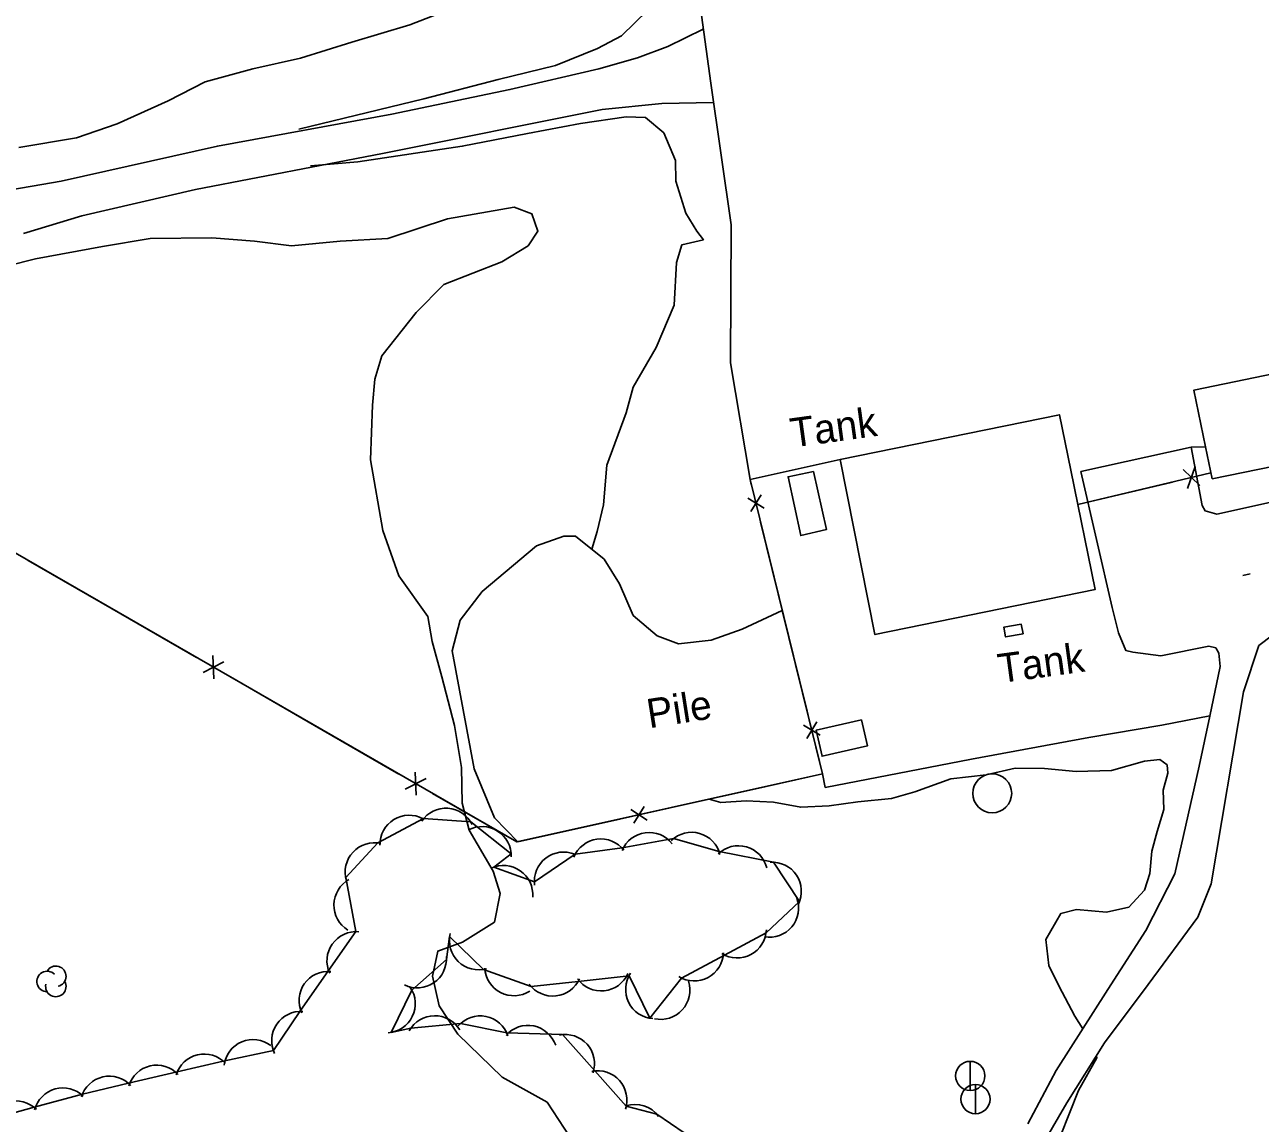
# Model space of a CAD drawing. Extents: x 643342 to 646936, y 5873857 to 5876103.
# Drawn here: x 645862.1 to 645989.1, y 5875514.5 to 5875627.4 of the extents above; entities that cross this region are included whole.
import ezdxf

# ---------------------------------------------------------------- set-up
doc = ezdxf.new("R2010")
doc.units = 0
for name, color, linetype in [('Niveau 19', 7, 'Continuous'), ('Niveau 2', 7, 'Continuous'), ('Niveau 21', 7, 'Continuous'), ('Niveau 3', 7, 'Continuous'), ('Niveau 31', 7, 'Continuous'), ('Niveau 33', 7, 'Continuous'), ('Niveau 36', 7, 'Continuous'), ('Niveau 37', 7, 'Continuous'), ('Niveau 44', 7, 'Continuous'), ('Niveau 57', 7, 'Continuous')]:
    doc.layers.add(name, color=color, linetype=linetype)

msp = doc.modelspace()

# ---------------------------------------------------------------- linework, layer by layer
at = {"layer": 'Niveau 19'}
for points in [[(645936.63, 5875580.67), (645934.6, 5875592.65), (645934.67, 5875606.84), (645932.59, 5875621.38), (645931.38, 5875630.15), (645932.04, 5875643.22), (645932.85, 5875648.57), (645934.53, 5875650.39), (645937.1, 5875651.48), (645954.04, 5875654.92), (645956.53, 5875656.71), (645957.95, 5875658.73), (645958.33, 5875660.53), (645958.77, 5875662.91), (645956.04, 5875678.99), (645953.32, 5875691.9), (645950.59, 5875700.71), (645949.61, 5875703.18), (645944.67, 5875717.25)], [(645981.95, 5875583.99), (645983.44, 5875584.02)], [(645944.08, 5875550.42), (645944.35, 5875549.04), (645959.39, 5875551.93), (645971.45, 5875554.15), (645978.93, 5875555.42), (645983.87, 5875556.38)]]:
    msp.add_lwpolyline(points, dxfattribs=at)
at = {"layer": 'Niveau 2'}
for points in [[(645861.47, 5875614.78), (645867.4, 5875615.77), (645871.59, 5875617.21), (645876.84, 5875619.59), (645880.62, 5875621.51), (645885.52, 5875622.86), (645890.44, 5875623.97), (645895.72, 5875625.59), (645901.68, 5875627.39), (645908.21, 5875629.91)], [(645926.12, 5875628.89), (645923.43, 5875626.26), (645920.94, 5875624.94), (645916.62, 5875623.2), (645910.74, 5875621.75), (645903.11, 5875619.77), (645890.27, 5875616.68)], [(645920.35, 5875573.52), (645920.91, 5875575.34), (645921.55, 5875578.05), (645921.92, 5875582.14), (645923.9, 5875587.51), (645924.61, 5875590.17), (645926.97, 5875594.23), (645928.83, 5875598.59), (645929.05, 5875602.95), (645929.61, 5875604.77), (645931.84, 5875605.3), (645931.16, 5875606.17), (645930.01, 5875608.04), (645929, 5875611.33), (645928.95, 5875613.43), (645927.75, 5875616.3), (645925.88, 5875617.85), (645923.88, 5875617.93), (645919.21, 5875617.26), (645913.76, 5875616.21), (645907.05, 5875614.91), (645896.33, 5875613.3), (645891.45, 5875612.9)], [(645918.11, 5875513.13), (645915.77, 5875516.71), (645911.14, 5875519.27), (645906.6, 5875523.68), (645904.69, 5875526.59), (645904, 5875529.64), (645904.54, 5875532.22), (645907.08, 5875533.14), (645910.38, 5875535.2), (645910.94, 5875538.14), (645910.22, 5875540.42), (645907.76, 5875544.63), (645907.04, 5875547.43), (645906.99, 5875551.07), (645906.27, 5875555.41), (645904.96, 5875560.38), (645903.97, 5875564.04), (645903.52, 5875566.58), (645900.53, 5875570.78), (645898.9, 5875575.43), (645897.63, 5875582.7), (645897.83, 5875588.3), (645898.07, 5875590.97), (645898.8, 5875593.39), (645902.3, 5875597.82), (645905.15, 5875600.71), (645911.12, 5875603.04), (645913.81, 5875604.68), (645914.82, 5875606.2), (645914.21, 5875607.95), (645912.38, 5875608.64), (645905.53, 5875607.44), (645899.41, 5875605.44), (645894.51, 5875605.15), (645889.51, 5875604.68), (645885.71, 5875605.15), (645881.32, 5875605.51), (645874.99, 5875605.42), (645870.1, 5875604.61), (645863.19, 5875603.34), (645860.34, 5875602.63)], [(645932.42, 5875547.82), (645933.63, 5875547.48), (645936.22, 5875547.64), (645939.02, 5875547.52), (645941.83, 5875547), (645944.75, 5875547.14), (645947.7, 5875547.54), (645951.17, 5875547.91), (645953.56, 5875548.57), (645957.26, 5875549.91), (645960.88, 5875550.32), (645963.88, 5875551), (645966.87, 5875550.99), (645970.13, 5875550.66), (645973.76, 5875550.76), (645977.17, 5875551.74), (645978.74, 5875551.9), (645979.5, 5875551.34), (645979.54, 5875550.49), (645979.06, 5875548.76), (645979.13, 5875546.75), (645978.47, 5875544.5), (645977.91, 5875542.48), (645977.69, 5875540.19), (645977.15, 5875538.49), (645975.56, 5875536.73), (645973.24, 5875536.22), (645970.16, 5875536.48), (645968.56, 5875536.08), (645967.01, 5875533.41), (645967.34, 5875530.72), (645968.36, 5875528.65), (645970, 5875525.54), (645970.82, 5875524.24)], [(645972.21, 5875521.47), (645972.26, 5875521.25), (645970.38, 5875517.91), (645968.52, 5875513.24), (645967.77, 5875509.63), (645966.59, 5875507.36), (645965.89, 5875505.2), (645964.16, 5875504.69), (645962.33, 5875504.72)]]:
    msp.add_lwpolyline(points, dxfattribs=at)
at = {"layer": 'Niveau 21'}
for points in [[(645931.82, 5875626.94), (645928.16, 5875625.15), (645925.06, 5875624), (645921.09, 5875622.85), (645911.95, 5875620.73), (645899.83, 5875618.21), (645881.89, 5875614.93), (645865.83, 5875611.31), (645853.46, 5875609.19)], [(645861.95, 5875605.93), (645867.95, 5875607.77), (645879.63, 5875610.45), (645898.85, 5875614.16), (645921.44, 5875618.7), (645927.57, 5875619.29), (645932.87, 5875619.4)], [(646003, 5875581.19), (645984.59, 5875577.12), (645983.38, 5875577.46), (645983.08, 5875578.01), (645981.95, 5875583.99), (645970.63, 5875581.49), (645973.82, 5875567.53), (645974.47, 5875564.9), (645975.25, 5875563.1), (645975.97, 5875562.94), (645978.83, 5875562.55), (645983.76, 5875563.54), (645984.48, 5875563.38), (645984.78, 5875562.83), (645984.93, 5875561.44), (645983.87, 5875556.37), (645982.79, 5875551.23), (645980.27, 5875540.16), (645977.28, 5875534.32), (645973.38, 5875528.27), (645968.09, 5875519.95), (645965.17, 5875514.46)], [(645916.11, 5875432.97), (645916.98, 5875434.72), (645918.62, 5875435.84), (645921.07, 5875438.1), (645924.38, 5875442.23), (645928.35, 5875448.78), (645930.73, 5875453.86), (645933.21, 5875460.14), (645935.59, 5875465.22), (645938.95, 5875468.76), (645943.76, 5875474.1), (645948.94, 5875480.42), (645952.34, 5875485.72), (645954.65, 5875491.38), (645958.1, 5875497.27), (645964.53, 5875508.6), (645969.16, 5875516.62), (645973.05, 5875522.8), (645977.54, 5875528.8), (645982.64, 5875535.69), (645984.02, 5875539.12), (645987.33, 5875558.85), (645988.91, 5875563.6), (645990.31, 5875564.69)]]:
    msp.add_lwpolyline(points, dxfattribs=at)
at = {"layer": 'Niveau 3'}
msp.add_line((645987.25, 5875570.82), (645988.03, 5875570.99), dxfattribs=at)
at = {"layer": 'Niveau 31'}
for points in [[(645984.11, 5875580.73), (645983.44, 5875584.02), (645982.24, 5875589.85), (645992.69, 5875591.99), (645992.15, 5875594.59), (645997.62, 5875595.71), (645999.15, 5875588.26), (646000.03, 5875583.99), (645984.11, 5875580.73)], [(645945.88, 5875582.71), (645968.41, 5875587.33), (645969.58, 5875581.63), (645972.09, 5875569.37), (645949.45, 5875564.73), (645945.88, 5875582.71)], [(645948.09, 5875555.99), (645948.71, 5875553.32), (645944.03, 5875552.24), (645943.41, 5875554.91), (645948.09, 5875555.99)]]:
    msp.add_lwpolyline(points, dxfattribs=at)
at = {"layer": 'Niveau 33'}
for points in [[(645943.13, 5875581.49), (645944.47, 5875575.52), (645941.84, 5875574.91), (645940.54, 5875580.95), (645943.13, 5875581.49)], [(645964.7, 5875564.82), (645962.88, 5875564.49), (645962.71, 5875565.5), (645964.5, 5875565.79), (645964.7, 5875564.82)]]:
    msp.add_lwpolyline(points, dxfattribs=at)
at = {"layer": 'Niveau 36'}
for points in [[(645959.25, 5875517.89), (645959.25, 5875520.89)], [(645959.79, 5875515.51), (645959.79, 5875518.51)]]:
    msp.add_lwpolyline(points, dxfattribs=at)
for centre, radius in [((645961.51, 5875548.42), 2), ((645959.25, 5875519.39), 1.5), ((645959.79, 5875517.01), 1.5)]:
    msp.add_circle(centre, radius, dxfattribs=at)
at = {"layer": 'Niveau 37'}
msp.add_line((645970.3, 5875578.1), (645983.98, 5875581.35), dxfattribs=at)
for points in [[(645912.67, 5875543.43), (645840.15, 5875585.19), (645786.72, 5875615.54), (645744.58, 5875639.47), (645661.64, 5875622.06)], [(645945.88, 5875582.71), (645936.63, 5875580.67), (645944.08, 5875550.42), (645912.67, 5875543.43)], [(645945.88, 5875582.71), (645936.63, 5875580.67), (645936.75, 5875580.17)], [(645981.58, 5875579.75), (645982.38, 5875582)], [(645981.12, 5875581.7), (645982.85, 5875580.05)], [(645970.3, 5875578.1), (645980.03, 5875580.41)], [(645936.38, 5875578.74), (645938.09, 5875577.71)], [(645936.72, 5875577.37), (645937.75, 5875579.08)], [(645937.71, 5875576.28), (645940.1, 5875566.57)], [(645871.09, 5875567.37), (645862.43, 5875572.36)], [(645879.75, 5875562.38), (645871.09, 5875567.37)], [(645940.1, 5875566.57), (645942.49, 5875556.86)], [(645882.54, 5875561.93), (645880.42, 5875560.85)], [(645881.54, 5875560.2), (645881.41, 5875562.58)], [(645891.88, 5875555.4), (645883.22, 5875560.39)], [(645900.54, 5875550.41), (645891.88, 5875555.4)], [(645942.12, 5875555.44), (645943.83, 5875554.4)], [(645942.45, 5875554.06), (645943.49, 5875555.78)], [(645943.45, 5875552.98), (645944.08, 5875550.42), (645936.91, 5875548.82)], [(645902.33, 5875548.23), (645902.2, 5875550.61)], [(645903.33, 5875549.96), (645901.2, 5875548.87)], [(645912.67, 5875543.43), (645904.01, 5875548.41)], [(645936.91, 5875548.82), (645927.16, 5875546.65)], [(645924.36, 5875546.75), (645926.05, 5875545.68)], [(645925.74, 5875547.06), (645924.67, 5875545.37)], [(645923.26, 5875545.78), (645913.51, 5875543.61)], [(645913.51, 5875543.61), (645912.67, 5875543.43)]]:
    msp.add_lwpolyline(points, dxfattribs=at)
at = {"layer": 'Niveau 44'}
for points in [[(645932.66, 5875511.61), (645927.04, 5875515.47), (645923.9, 5875516.28), (645920.67, 5875519.9), (645917.34, 5875523.64), (645911.63, 5875523.82), (645906.87, 5875524.77), (645901.78, 5875524.3), (645899.73, 5875523.85), (645901.87, 5875528.21), (645905.43, 5875531.34), (645905.75, 5875533.71), (645909.25, 5875530.34), (645914.13, 5875528.58), (645918.96, 5875529.1), (645924.19, 5875529.68), (645926.33, 5875525.33), (645929.58, 5875529.45), (645933.99, 5875531.81), (645938.27, 5875534.1), (645941.72, 5875537.32), (645939.02, 5875541.36), (645933.44, 5875542.45), (645928.77, 5875543.78), (645923.47, 5875542.81), (645918.65, 5875542.17), (645914.46, 5875539.32), (645910.31, 5875540.84), (645912.08, 5875542.21), (645907.92, 5875545.49), (645903.07, 5875545.83), (645898.39, 5875543.33), (645895.08, 5875539.78), (645896.1, 5875534.22), (645893.32, 5875530.24), (645890.37, 5875526.02), (645887.66, 5875522)], [(645887.66, 5875522), (645882.49, 5875520.91), (645877.76, 5875519.8), (645872.75, 5875518.64), (645868.03, 5875517.53), (645863.05, 5875516.17), (645858.38, 5875514.87)]]:
    msp.add_lwpolyline(points, dxfattribs=at)
for centre, radius, start, end in [((645905.37, 5875543.9), 3, 26.0843, 146.0623), ((645905.37, 5875543.9), 3, 26.0843, 146.0623), ((645905.37, 5875543.9), 3, 26.0843, 146.0623), ((645901.59, 5875543.18), 3, 61.521, 181.4989), ((645901.59, 5875543.18), 3, 61.521, 181.4989), ((645901.59, 5875543.18), 3, 61.521, 181.4989), ((645909.08, 5875542.01), 3, 357.7192, 117.6971), ((645909.08, 5875542.01), 3, 357.7192, 117.6971), ((645909.08, 5875542.01), 3, 357.7192, 117.6971), ((645926.25, 5875541.41), 3, 37.6317, 157.6096), ((645926.25, 5875541.41), 3, 37.6317, 157.6096), ((645926.25, 5875541.41), 3, 37.6317, 157.6096), ((645930.62, 5875541.42), 3, 14.1132, 134.0911), ((645930.62, 5875541.42), 3, 14.1132, 134.0911), ((645930.62, 5875541.42), 3, 14.1132, 134.0911), ((645898.02, 5875540.35), 3, 76.9978, 196.9758), ((645898.02, 5875540.35), 3, 76.9978, 196.9758), ((645898.02, 5875540.35), 3, 76.9978, 196.9758), ((645921.29, 5875540.74), 3, 37.6317, 157.6096), ((645921.29, 5875540.74), 3, 37.6317, 157.6096), ((645921.29, 5875540.74), 3, 37.6317, 157.6096), ((645935.43, 5875540.04), 3, 14.1132, 134.0911), ((645935.43, 5875540.04), 3, 14.1132, 134.0911), ((645935.43, 5875540.04), 3, 14.1132, 134.0911), ((645917.46, 5875539.39), 3, 67.4679, 187.4459), ((645917.46, 5875539.39), 3, 67.4679, 187.4459), ((645917.46, 5875539.39), 3, 67.4679, 187.4459), ((645911.3, 5875538.01), 3, 355.2315, 115.2094), ((645911.3, 5875538.01), 3, 355.2315, 115.2094), ((645911.3, 5875538.01), 3, 355.2315, 115.2094), ((645938.9, 5875538.36), 3, 333.7229, 93.7008), ((645938.9, 5875538.36), 3, 333.7229, 93.7008), ((645938.9, 5875538.36), 3, 333.7229, 93.7008), ((645896.86, 5875536.94), 3, 118.8402, 238.8182), ((645896.86, 5875536.94), 3, 118.8402, 238.8182), ((645896.86, 5875536.94), 3, 118.8402, 238.8182), ((645938.62, 5875536.64), 3, 259.9714, 19.9493), ((645938.62, 5875536.64), 3, 259.9714, 19.9493), ((645938.62, 5875536.64), 3, 259.9714, 19.9493), ((645896.15, 5875531.22), 3, 84.995, 204.9729), ((645896.15, 5875531.22), 3, 84.995, 204.9729), ((645896.15, 5875531.22), 3, 84.995, 204.9729), ((645908.73, 5875533.29), 3, 165.9814, 285.9593), ((645908.73, 5875533.29), 3, 165.9814, 285.9593), ((645908.73, 5875533.29), 3, 165.9814, 285.9593), ((645935.3, 5875534.51), 3, 238.1636, 358.1415), ((645935.3, 5875534.51), 3, 238.1636, 358.1415), ((645935.3, 5875534.51), 3, 238.1636, 358.1415), ((645902.43, 5875531.44), 3, 244.0878, 4.0657), ((645902.43, 5875531.44), 3, 244.0878, 4.0657), ((645902.43, 5875531.44), 3, 244.0878, 4.0657), ((645930.89, 5875532.15), 3, 238.1636, 358.1415), ((645930.89, 5875532.15), 3, 238.1636, 358.1415), ((645930.89, 5875532.15), 3, 238.1636, 358.1415), ((645864.39, 5875529.1), 1.05, 44.1154, 269.804), ((645865.29, 5875529.63), 1.05, 282.2692, 149.7263), ((645893.28, 5875527.13), 3, 84.995, 204.9729), ((645893.28, 5875527.13), 3, 84.995, 204.9729), ((645893.28, 5875527.13), 3, 84.995, 204.9729), ((645912.36, 5875530.63), 3, 182.9388, 302.9167), ((645912.36, 5875530.63), 3, 182.9388, 302.9167), ((645912.36, 5875530.63), 3, 182.9388, 302.9167), ((645926.84, 5875528.28), 3, 146.2492, 266.2272), ((645926.84, 5875528.28), 3, 146.2492, 266.2272), ((645926.84, 5875528.28), 3, 146.2492, 266.2272), ((645865.29, 5875528.58), 1.05, 166.9369, 29.6212), ((645916.36, 5875530.59), 3, 216.1013, 336.0792), ((645916.36, 5875530.59), 3, 216.1013, 336.0792), ((645916.36, 5875530.59), 3, 216.1013, 336.0792), ((645921.33, 5875531.12), 3, 216.1013, 336.0792), ((645921.33, 5875531.12), 3, 216.1013, 336.0792), ((645921.33, 5875531.12), 3, 216.1013, 336.0792), ((645927.44, 5875528.2), 3, 257.7151, 17.6931), ((645927.44, 5875528.2), 3, 257.7151, 17.6931), ((645927.44, 5875528.2), 3, 257.7151, 17.6931), ((645899.22, 5875526.81), 3, 273.9492, 33.9271), ((645899.22, 5875526.81), 3, 273.9492, 33.9271), ((645899.22, 5875526.81), 3, 273.9492, 33.9271), ((645890.47, 5875523.02), 3, 86.0321, 206.0101), ((645890.47, 5875523.02), 3, 86.0321, 206.0101), ((645890.47, 5875523.02), 3, 86.0321, 206.0101), ((645904.23, 5875522.58), 3, 30.8996, 150.8776), ((645904.23, 5875522.58), 3, 30.8996, 150.8776), ((645904.23, 5875522.58), 3, 30.8996, 150.8776), ((645908.9, 5875522.56), 3, 18.7364, 138.7143), ((645908.9, 5875522.56), 3, 18.7364, 138.7143), ((645908.9, 5875522.56), 3, 18.7364, 138.7143), ((645913.81, 5875521.58), 3, 18.7364, 138.7143), ((645913.81, 5875521.58), 3, 18.7364, 138.7143), ((645913.81, 5875521.58), 3, 18.7364, 138.7143), ((645917.64, 5875520.65), 3, 341.7379, 101.7159), ((645917.64, 5875520.65), 3, 341.7379, 101.7159), ((645917.64, 5875520.65), 3, 341.7379, 101.7159), ((645885.55, 5875520.12), 3, 52.7347, 172.7127), ((645885.55, 5875520.12), 3, 52.7347, 172.7127), ((645885.55, 5875520.12), 3, 52.7347, 172.7127), ((645880.53, 5875518.64), 3, 43.1413, 163.1192), ((645880.53, 5875518.64), 3, 43.1413, 163.1192), ((645880.53, 5875518.64), 3, 43.1413, 163.1192), ((645875.66, 5875517.5), 3, 43.1413, 163.1192), ((645875.66, 5875517.5), 3, 43.1413, 163.1192), ((645875.66, 5875517.5), 3, 43.1413, 163.1192), ((645920.97, 5875516.92), 3, 341.7379, 101.7159), ((645920.97, 5875516.92), 3, 341.7379, 101.7159), ((645920.97, 5875516.92), 3, 341.7379, 101.7159), ((645870.79, 5875516.37), 3, 43.1413, 163.1192), ((645870.79, 5875516.37), 3, 43.1413, 163.1192), ((645870.79, 5875516.37), 3, 43.1413, 163.1192), ((645866.01, 5875515.16), 3, 45.5876, 165.5655), ((645866.01, 5875515.16), 3, 45.5876, 165.5655), ((645866.01, 5875515.16), 3, 45.5876, 165.5655), ((645861.19, 5875513.82), 3, 45.5876, 165.5655), ((645861.19, 5875513.82), 3, 45.5876, 165.5655), ((645861.19, 5875513.82), 3, 45.5876, 165.5655), ((645924.81, 5875513.46), 3, 36.1616, 108.4996), ((645924.81, 5875513.46), 3, 36.1616, 108.4996), ((645924.81, 5875513.46), 3, 36.1616, 108.4996)]:
    msp.add_arc(centre, radius, start, end, dxfattribs=at)
at = {"layer": 'Niveau 57'}
for points in [[(645912.76, 5875543.45), (645910.37, 5875545.9), (645908.29, 5875550.96), (645906.02, 5875563.06), (645906.84, 5875566.21), (645909.1, 5875569.15), (645914.68, 5875573.85), (645917.5, 5875574.86), (645918.68, 5875574.86), (645921.64, 5875572.48), (645923.2, 5875569.95), (645924.62, 5875566.7), (645927.08, 5875564.61), (645929.28, 5875563.79), (645932.64, 5875564.15), (645935.8, 5875565.3), (645939.94, 5875567.21)], [(645939.94, 5875567.21), (645944.08, 5875550.42), (645912.76, 5875543.45)]]:
    msp.add_lwpolyline(points, dxfattribs=at)

# ---------------------------------------------------------------- texts
at = {"layer": 'Niveau 33'}
for p in [(645940.97, 5875583.95), (645962.3, 5875559.74)]:
    msp.add_text('Tank', height=3, rotation=7.792, dxfattribs=at).set_placement(p)
at = {"layer": 'Niveau 57'}
msp.add_text('Pile', height=3, rotation=8.9405, dxfattribs=at).set_placement((645926.26, 5875555.1))

doc.saveas('drawing.dxf')
